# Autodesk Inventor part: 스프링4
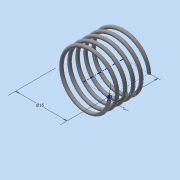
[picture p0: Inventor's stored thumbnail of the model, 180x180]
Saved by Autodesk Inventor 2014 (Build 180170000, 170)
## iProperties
Created: 2015-06
Part Number: 스프링4
Material: 강철, 연강
Document SubType Name: Modeling
Designer: MYHOME
Density: 1 g/cm^3
Appearance: 강철
Author: MYHOME
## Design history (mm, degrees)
sketch "스케치1"
  geometry: L1 (0, 0)-(8, 0); L2 (8, 0)-(8, 12.5); L3 (8, 12.5)-(0, 12.5); L4 (0, 12.5)-(0, 0); C1 r 0.5 at (8, 0)
  constraints: 8 end point, 2 parallel, 1 centre point, 1 coincident, 1 horizontal, 1 perpendicular
  dimensions: "d0" = 16 diameter of L2 L4; "d1" = 12.5 distance of L1.end L2.end (derived); "d2" = 1 diameter of C1
feature "코일1" sketch "스케치1" pitch "d3" = 10; turns "d5" = 5; dims "d4" = 12.5 (= d1), "d6" = 0, angle "d7" = 90 deg, angle "d8" = 90 deg, "d9" = 0, "d10" = 0
node "작업 평면1"
sketch "스케치2"
  geometry: L1 (-8.5, 0)-(-7.5, 0) reference; 1 further point
  constraints: 1 horizontal alignment
extrude "돌출1" cut sketch "스케치2" stored distance "d12" = 10; taper "d13" = 0 deg
node "작업 평면2"
sketch "스케치3"
  geometry: L1 (8.5, 0)-(7.5, 0) reference; 1 further point
  constraints: 1 horizontal alignment
extrude "돌출2" cut sketch "스케치3" stored distance "d15" = 10; taper "d16" = 0 deg
node "솔리드1"
node "절단 모서리 투영1"
node "절단 모서리 투영2"
other parameters: "d11" = 0, "d14" = -12.5 (= -d1)
